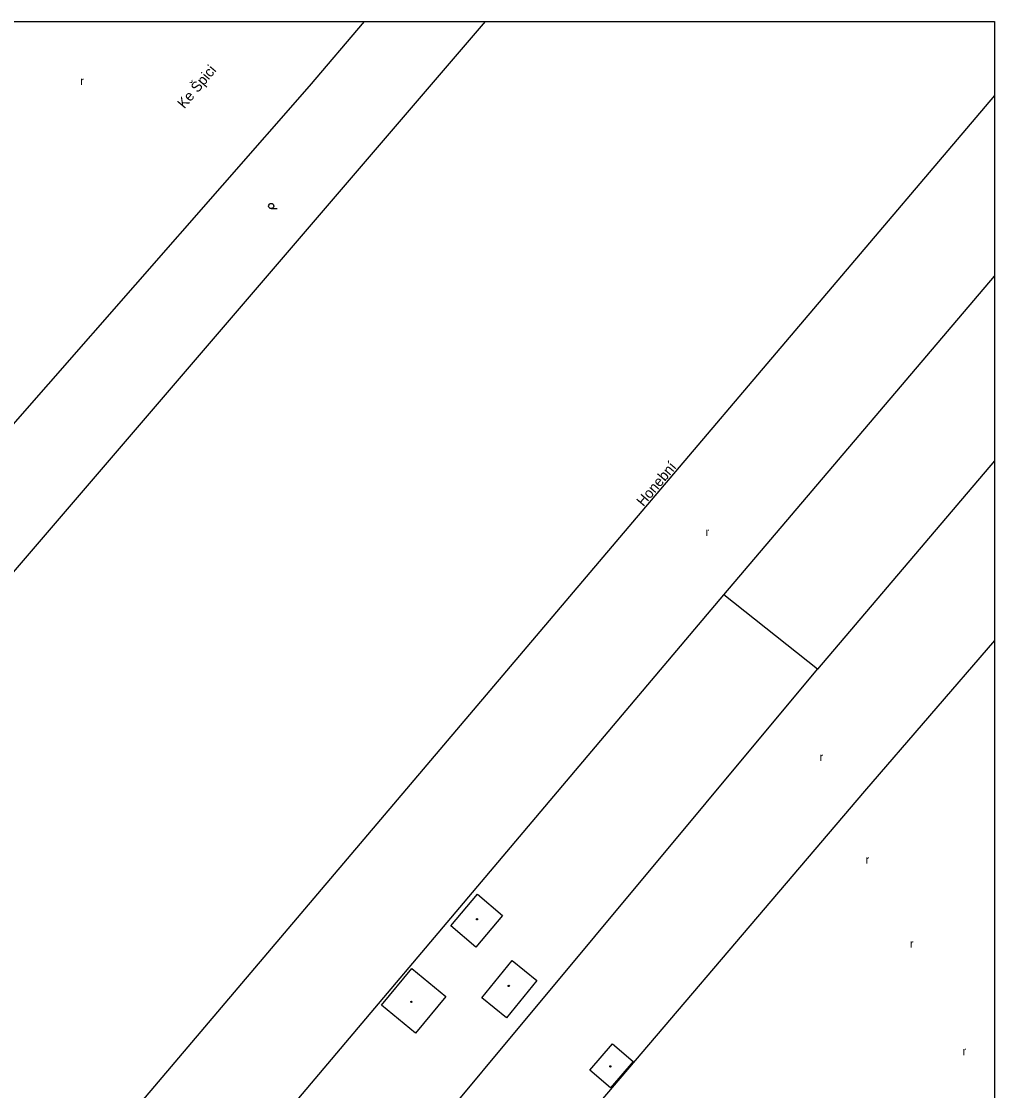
# Model space of a CAD drawing. Extents: x -594386 to -594050, y -1167541 to -1167175.
# Drawn here: x -594190.8 to -594049.8, y -1167330.4 to -1167175.4 of the extents above; entities that cross this region are included whole.
import ezdxf

# ---------------------------------------------------------------- set-up
doc = ezdxf.new("R2010")
doc.units = 0
for name, color, linetype in [('Level 36', 7, 'Continuous'), ('Level 39', 7, 'Continuous'), ('Vrstva 50', 7, 'Continuous'), ('Vrstva 51', 7, 'Continuous'), ('Vrstva 52', 7, 'Continuous'), ('Vrstva 63', 7, 'Continuous')]:
    doc.layers.add(name, color=color, linetype=linetype)

msp = doc.modelspace()

# ---------------------------------------------------------------- linework, layer by layer
at = {"layer": 'Level 36'}
msp.add_line((-594154.62, -1167202.57), (-594153.75, -1167202.57), dxfattribs=at)
msp.add_circle((-594154.62, -1167202.19), 0.375, dxfattribs=at)
at = {"layer": 'Level 39'}
for centre, radius in [((-594124.79, -1167305.56), 0.09), ((-594124.79, -1167305.56), 0.0398), ((-594120.19, -1167315.23), 0.09), ((-594120.19, -1167315.23), 0.0398), ((-594134.3, -1167317.53), 0.09), ((-594134.3, -1167317.53), 0.0398), ((-594105.46, -1167326.89), 0.09), ((-594105.46, -1167326.89), 0.0398)]:
    msp.add_circle(centre, radius, dxfattribs=at)
at = {"layer": 'Vrstva 51'}
for p, q in [((-594229, -1167298.38), (-594123.58, -1167175.43)), ((-594141.14, -1167175.43), (-594149.13, -1167184.83)), ((-594049.75, -1167186.18), (-594102.27, -1167248.02)), ((-594089, -1167258.56), (-594049.75, -1167212.36)), ((-594049.75, -1167239.1), (-594075.44, -1167269.34)), ((-594049.75, -1167265.17), (-594068.61, -1167287))]:
    msp.add_line(p, q, dxfattribs=at)
for points in [[(-594149.13, -1167184.83), (-594237.46, -1167285.58)], [(-594102.27, -1167248.02), (-594200.89, -1167364.28)], [(-594181.54, -1167368.12), (-594089, -1167258.56)], [(-594075.44, -1167269.34), (-594089, -1167258.56)], [(-594172.52, -1167385.86), (-594075.44, -1167269.34)], [(-594068.61, -1167287), (-594162.26, -1167396.94)]]:
    msp.add_lwpolyline(points, dxfattribs=at)
at = {"layer": 'Vrstva 52'}
for points in [[(-594128.59, -1167306.5), (-594124.71, -1167301.95)], [(-594124.71, -1167301.95), (-594121.09, -1167305.03)], [(-594121.09, -1167305.03), (-594124.97, -1167309.59)], [(-594124.97, -1167309.59), (-594128.59, -1167306.5)], [(-594138.63, -1167318.02), (-594134.25, -1167312.7)], [(-594134.25, -1167312.7), (-594129.32, -1167316.75)], [(-594124.07, -1167316.97), (-594119.69, -1167311.54)], [(-594119.69, -1167311.54), (-594116.12, -1167314.42)], [(-594116.12, -1167314.42), (-594120.51, -1167319.85)], [(-594129.32, -1167316.75), (-594133.7, -1167322.07)], [(-594120.51, -1167319.85), (-594124.07, -1167316.97)], [(-594133.7, -1167322.07), (-594138.63, -1167318.02)], [(-594108.41, -1167327.45), (-594105.13, -1167323.62)], [(-594105.13, -1167323.62), (-594102.17, -1167326.16)], [(-594102.17, -1167326.16), (-594105.44, -1167329.99)], [(-594105.44, -1167329.99), (-594108.41, -1167327.45)]]:
    msp.add_lwpolyline(points, dxfattribs=at)
at = {"layer": 'Vrstva 63'}
msp.add_lwpolyline([(-594386.36, -1167175.43), (-594049.75, -1167175.43), (-594049.75, -1167540.79), (-594386.36, -1167540.79)], close=True, dxfattribs=at)

# ---------------------------------------------------------------- texts
at = {"layer": 'Level 36'}
for p in [(-594182.32, -1167184.66), (-594091.67, -1167250.02), (-594075.13, -1167282.64), (-594068.46, -1167297.51), (-594062.02, -1167309.69), (-594054.41, -1167325.27)]:
    msp.add_text('r', height=1.2, dxfattribs=at).set_placement(p)
at = {"layer": 'Vrstva 50'}
for s, rotation, p in [('Ke Špici', 49.9707, (-594167.22, -1167188.18)), ('Honební', 49.7704, (-594100.67, -1167245.84))]:
    msp.add_text(s, height=1.5, rotation=rotation, dxfattribs=at).set_placement(p)

doc.saveas('drawing.dxf')
